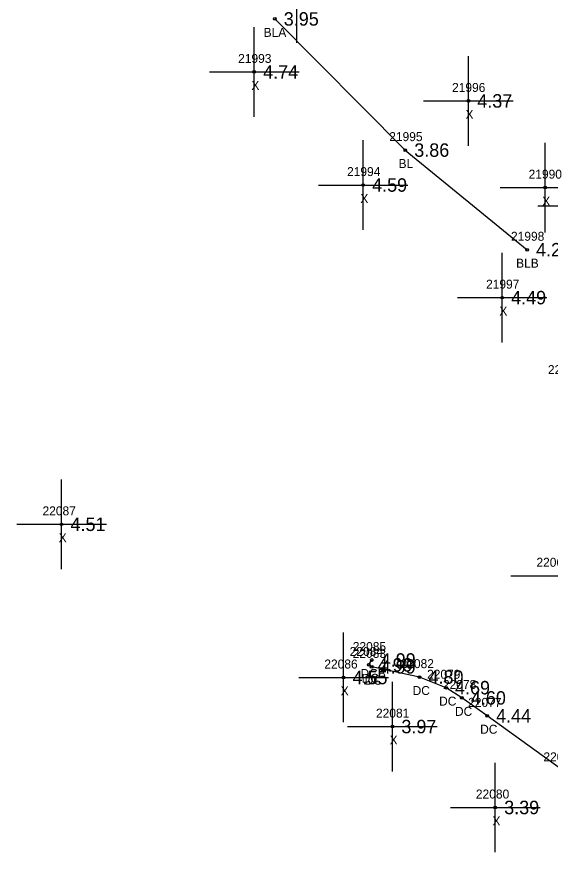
# Model space of a CAD drawing. Extents: x 2608745 to 2610333, y 641917 to 643463.
# Drawn here: x 2609899.1 to 2609958.6, y 641983.3 to 642076.5 of the extents above; entities that cross this region are included whole.
import ezdxf

# ---------------------------------------------------------------- set-up
doc = ezdxf.new("R2010")
doc.units = 0
for name, color, linetype in [('RD_DTM_BkLn1', 7, 'Continuous'), ('RD_DTM_BkLn_txCode', 7, 'Continuous'), ('RD_EX_Conc', 7, 'Continuous'), ('RD_EX_Conc_txCode', 7, 'Continuous'), ('RD_EX_Misc', 7, 'Continuous'), ('RD_EX_Misc_txCode', 7, 'Continuous'), ('RD_EX_TX_Conc_ELEV', 7, 'Continuous'), ('RD_EX_TX_Misc_ELEV', 7, 'Continuous'), ('RD_SMD_Locator', 7, 'Continuous')]:
    doc.layers.add(name, color=color, linetype=linetype)

msp = doc.modelspace()

# ---------------------------------------------------------------- linework, layer by layer
at = {"layer": 'RD_DTM_BkLn1'}
msp.add_lwpolyline([(2609927.873, 642076.278), (2609942.438, 642061.641), (2609956.024, 642050.524)], dxfattribs=at)
at = {"layer": 'RD_EX_Conc'}
msp.add_lwpolyline([(2609969.557, 641985.649), (2609959.989, 641992.436), (2609951.566, 641998.518), (2609948.754, 642000.513), (2609946.984, 642001.655), (2609944.027, 642002.836), (2609938.684, 642003.981), (2609938.35, 642004.199), (2609938.692, 642004.745)], dxfattribs=at)
at = {"layer": 'RD_EX_Misc'}
for p, q in [((2609930.328, 642073.619), (2609930.328, 642083.619)), ((2609925.577, 642065.364), (2609925.577, 642075.364)), ((2609949.471, 642062.129), (2609949.471, 642072.129)), ((2609920.577, 642070.364), (2609930.577, 642070.364)), ((2609944.471, 642067.129), (2609954.471, 642067.129)), ((2609937.733, 642052.741), (2609937.733, 642062.741)), ((2609958.029, 642052.455), (2609958.029, 642062.455)), ((2609932.733, 642057.741), (2609942.733, 642057.741)), ((2609953.029, 642057.455), (2609963.029, 642057.455)), ((2609957.219, 642055.404), (2609967.219, 642055.404)), ((2609953.245, 642040.178), (2609953.245, 642050.178)), ((2609948.245, 642045.178), (2609958.245, 642045.178)), ((2609904.078, 642014.887), (2609904.078, 642024.887)), ((2609899.078, 642019.887), (2609909.078, 642019.887)), ((2609954.207, 642014.147), (2609964.207, 642014.147)), ((2609935.543, 641997.794), (2609935.543, 642007.794)), ((2609930.543, 642002.794), (2609940.543, 642002.794)), ((2609941, 641992.317), (2609941, 642002.317)), ((2609936, 641997.317), (2609946, 641997.317)), ((2609952.47, 641983.288), (2609952.47, 641993.288)), ((2609947.47, 641988.288), (2609957.47, 641988.288))]:
    msp.add_line(p, q, dxfattribs=at)
at = {"layer": 'RD_SMD_Locator'}
for centre in [(2609927.873, 642076.278), (2609925.577, 642070.364), (2609949.471, 642067.129), (2609942.438, 642061.641), (2609937.733, 642057.741), (2609958.029, 642057.455), (2609956.024, 642050.524), (2609953.245, 642045.178), (2609904.078, 642019.887), (2609938.692, 642004.745), (2609938.35, 642004.199), (2609938.684, 642003.981), (2609935.543, 642002.794), (2609944.027, 642002.836), (2609946.984, 642001.655), (2609948.754, 642000.513), (2609951.566, 641998.518), (2609941, 641997.317), (2609952.47, 641988.288)]:
    msp.add_circle(centre, 0.15, dxfattribs=at)

# ---------------------------------------------------------------- texts
at = {"layer": 'RD_DTM_BkLn_txCode'}
for s, p in [('BLA', (2609926.629, 642074.278)), ('21995', (2609940.643, 642062.641)), ('BL', (2609941.682, 642059.641)), ('21998', (2609954.229, 642051.524)), ('BLB', (2609954.796, 642048.524)), ('22000', (2609958.351, 642036.646))]:
    msp.add_text(s, height=1, dxfattribs=at).set_placement(p)
at = {"layer": 'RD_EX_Conc_txCode'}
for s, p in [('22085', (2609936.573, 642005.745)), ('22084', (2609936.232, 642005.199)), ('22083', (2609936.566, 642004.981)), ('22082', (2609941.909, 642003.836)), ('DCB', (2609937.44, 642002.745)), ('22079', (2609944.866, 642002.655)), ('DC', (2609937.571, 642002.199)), ('DC', (2609937.904, 642001.981)), ('DC', (2609943.248, 642000.836)), ('22078', (2609946.635, 642001.513)), ('DC', (2609946.205, 641999.655)), ('22077', (2609949.447, 641999.518)), ('DC', (2609947.974, 641998.513)), ('DC', (2609950.786, 641996.518)), ('22076', (2609957.848, 641993.436))]:
    msp.add_text(s, height=1, dxfattribs=at).set_placement(p)
at = {"layer": 'RD_EX_Misc_txCode'}
for s, p in [('21993', (2609923.782, 642071.364)), ('X', (2609925.262, 642068.364)), ('21996', (2609947.652, 642068.129)), ('X', (2609949.156, 642065.129)), ('21994', (2609935.938, 642058.741)), ('21990', (2609956.194, 642058.455)), ('X', (2609937.418, 642055.741)), ('X', (2609957.714, 642055.455)), ('21997', (2609951.449, 642046.178)), ('X', (2609952.93, 642043.178)), ('22087', (2609901.959, 642020.887)), ('X', (2609903.763, 642017.887)), ('22068', (2609957.066, 642015.147)), ('22086', (2609933.402, 642003.794)), ('X', (2609935.228, 642000.794)), ('22081', (2609939.165, 641998.317)), ('X', (2609940.685, 641995.317)), ('22080', (2609950.313, 641989.288)), ('X', (2609952.155, 641986.288))]:
    msp.add_text(s, height=1, dxfattribs=at).set_placement(p)
at = {"layer": 'RD_EX_TX_Conc_ELEV'}
for s, p in [('4.99', (2609939.692, 642003.995)), ('4.99', (2609939.35, 642003.449)), ('4.99', (2609939.684, 642003.231)), ('4.80', (2609945.027, 642002.086)), ('4.69', (2609947.984, 642000.905)), ('4.60', (2609949.754, 641999.763)), ('4.44', (2609952.566, 641997.768))]:
    msp.add_text(s, height=1.5, dxfattribs=at).set_placement(p)
at = {"layer": 'RD_EX_TX_Misc_ELEV'}
for s, p in [('3.95', (2609928.873, 642075.528)), ('4.74', (2609926.577, 642069.614)), ('4.37', (2609950.471, 642066.379)), ('3.86', (2609943.438, 642060.891)), ('4.59', (2609938.733, 642056.991)), ('4.23', (2609957.024, 642049.774)), ('4.49', (2609954.245, 642044.428)), ('4.51', (2609905.078, 642019.137)), ('4.55', (2609936.543, 642002.044)), ('3.97', (2609942, 641996.567)), ('3.39', (2609953.47, 641987.538))]:
    msp.add_text(s, height=1.5, dxfattribs=at).set_placement(p)

doc.saveas('drawing.dxf')
